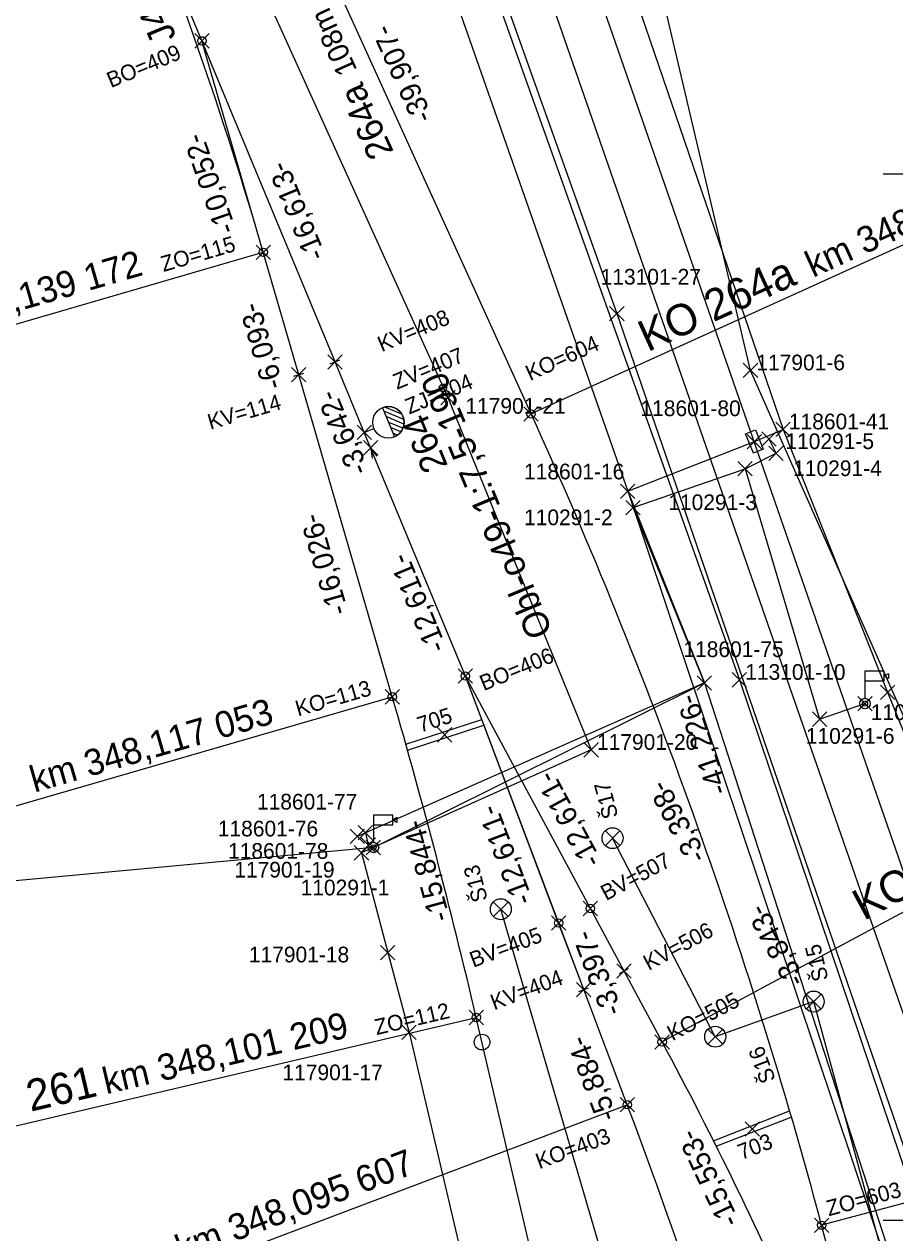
# Model space of a CAD drawing. Extents: x -821029 to -820632, y -1070881 to -1069931.
# Drawn here: x -820842.3 to -820800.7, y -1070400.6 to -1070342.9 of the extents above; entities that cross this region are included whole.
import ezdxf

# ---------------------------------------------------------------- set-up
doc = ezdxf.new("R2010")
doc.units = 0
for name, color, linetype in [('_PS_SO_číslo', 7, 'Continuous'), ('PS-11-02-31', 7, 'Continuous'), ('PS-11-02-41', 7, 'Continuous'), ('PS-11-02-91', 7, 'Continuous'), ('PS-11-02-92', 7, 'Continuous'), ('Sit', 7, 'Continuous'), ('SO-11-10-01', 7, 'Continuous'), ('SO-11-31-01', 7, 'Continuous'), ('SO-11-50-01', 7, 'Continuous'), ('SO-11-79-01', 7, 'Continuous'), ('SO-11-86-01', 7, 'Continuous'), ('Sttaniceni a namezniky', 7, 'Continuous'), ('VB_PS-11-02-91', 7, 'Continuous'), ('VB_SO-11-10-01', 7, 'Continuous'), ('VB_SO-11-31-01', 7, 'Continuous'), ('VB_SO-11-79-01', 7, 'Continuous'), ('VB_SO-11-86-01', 7, 'Continuous')]:
    doc.layers.add(name, color=color, linetype=linetype)

msp = doc.modelspace()

# ---------------------------------------------------------------- linework, layer by layer
at = {"layer": '_PS_SO_číslo'}
msp.add_line((-820825.628, -1070382.193), (-820859.303, -1070385.322), dxfattribs=at)
at = {"layer": 'PS-11-02-31'}
for points in [[(-820959.278, -1070122.218), (-820934.84, -1070144.095), (-820933.002, -1070146.602), (-820925.146, -1070161.738), (-820918.63, -1070175.611), (-820911.367, -1070188.874), (-820902.582, -1070186.65), (-820896.686, -1070196.978), (-820870.459, -1070236.453), (-820846.568, -1070277.079), (-820842.598, -1070282.108), (-820813.472, -1070365.169), (-820809.802, -1070374.33), (-820792.803, -1070426.722), (-820792.342, -1070428.474), (-820790.079, -1070430.856), (-820788.925, -1070435.581), (-820780.392, -1070470.858), (-820770.551, -1070511.609), (-820767.886, -1070524.681), (-820765.297, -1070562.399), (-820759.609, -1070562.181)], [(-820834.739, -1070280.72), (-820830.77, -1070287.401), (-820826.598, -1070295.778), (-820822.74, -1070307.417), (-820822.402, -1070310.542), (-820820.817, -1070316.363), (-820815.079, -1070335.816), (-820806.043, -1070362.212), (-820801.047, -1070374.777), (-820795.979, -1070387.28), (-820794.84, -1070387.997), (-820792.153, -1070393.193), (-820783.482, -1070412.233), (-820783.598, -1070416.458), (-820783.598, -1070418.019), (-820782.431, -1070424.351)], [(-820813.213, -1070365.954), (-820807.856, -1070364.093), (-820806.374, -1070363.352), (-820806.71, -1070362.68)], [(-820825.628, -1070382.193), (-820809.802, -1070374.33)]]:
    msp.add_lwpolyline(points, dxfattribs=at)
msp.add_lwpolyline([(-820807.368, -1070362.238), (-820806.994, -1070363.166), (-820807.458, -1070363.353), (-820807.832, -1070362.425)], close=True, dxfattribs=at)
at = {"layer": 'PS-11-02-41'}
for points in [[(-820882.988, -1070201.129), (-820875.537, -1070207.75), (-820872.787, -1070212.312), (-820866.572, -1070222.102), (-820863.695, -1070232.226), (-820854.155, -1070247.197), (-820844.785, -1070263.708), (-820834.739, -1070280.72), (-820830.77, -1070287.401), (-820826.598, -1070295.778), (-820822.74, -1070307.417), (-820822.402, -1070310.542), (-820820.817, -1070316.363), (-820815.079, -1070335.816), (-820806.043, -1070362.212), (-820801.047, -1070374.777), (-820795.979, -1070387.28), (-820794.84, -1070387.997), (-820792.153, -1070393.193), (-820783.482, -1070412.233), (-820783.598, -1070416.458), (-820783.598, -1070418.019), (-820782.431, -1070424.351)], [(-820813.472, -1070365.169), (-820807.413, -1070362.796), (-820806.043, -1070362.212)]]:
    msp.add_lwpolyline(points, dxfattribs=at)
at = {"layer": 'PS-11-02-91'}
for p, q in [((-820802.127, -1070374.234), (-820802.127, -1070375.064)), ((-820801.004, -1070373.887), (-820801.204, -1070374.003)), ((-820801.004, -1070374.118), (-820801.204, -1070374.003)), ((-820801.004, -1070373.887), (-820801.004, -1070374.118)), ((-820802.127, -1070375.314), (-820802.127, -1070375.314)), ((-820825.628, -1070381.113), (-820825.628, -1070381.943)), ((-820824.505, -1070380.767), (-820824.704, -1070380.882)), ((-820824.505, -1070380.998), (-820824.704, -1070380.882)), ((-820824.505, -1070380.767), (-820824.505, -1070380.998)), ((-820825.628, -1070382.193), (-820825.628, -1070382.193))]:
    msp.add_line(p, q, dxfattribs=at)
for points in [[(-820825.628, -1070382.193), (-820809.802, -1070374.33), (-820813.213, -1070365.954), (-820807.856, -1070364.093), (-820806.374, -1070363.352), (-820806.71, -1070362.68)], [(-820807.856, -1070364.093), (-820804.293, -1070376.062), (-820802.127, -1070375.314)]]:
    msp.add_lwpolyline(points, dxfattribs=at)
for points in [[(-820801.204, -1070373.772), (-820802.127, -1070373.772), (-820802.127, -1070374.234), (-820801.204, -1070374.234)], [(-820824.704, -1070380.651), (-820825.628, -1070380.651), (-820825.628, -1070381.113), (-820824.704, -1070381.113)]]:
    msp.add_lwpolyline(points, close=True, dxfattribs=at)
for centre, radius in [((-820802.127, -1070375.314), 0.25), ((-820802.127, -1070375.314), 0.125), ((-820825.628, -1070382.193), 0.25), ((-820825.628, -1070382.193), 0.125)]:
    msp.add_circle(centre, radius, dxfattribs=at)
at = {"layer": 'PS-11-02-92'}
for points in [[(-820882.988, -1070201.129), (-820875.537, -1070207.75), (-820872.787, -1070212.312), (-820866.572, -1070222.102), (-820863.695, -1070232.226), (-820854.155, -1070247.197), (-820844.785, -1070263.708), (-820834.739, -1070280.72), (-820830.77, -1070287.401), (-820826.598, -1070295.778), (-820822.74, -1070307.417), (-820822.402, -1070310.542), (-820820.817, -1070316.363), (-820815.079, -1070335.816), (-820806.043, -1070362.212), (-820801.047, -1070374.777), (-820795.979, -1070387.28), (-820794.84, -1070387.997), (-820792.153, -1070393.193), (-820783.482, -1070412.233), (-820783.598, -1070416.458), (-820783.598, -1070418.019), (-820782.431, -1070424.351)], [(-820813.472, -1070365.169), (-820807.413, -1070362.796), (-820806.043, -1070362.212)]]:
    msp.add_lwpolyline(points, dxfattribs=at)
at = {"layer": 'Sit'}
for p, q in [((-820801.25, -1070350), (-820800, -1070350)), ((-820801.25, -1070400), (-820800, -1070400))]:
    msp.add_line(p, q, dxfattribs=at)
at = {"layer": 'SO-11-10-01'}
for p, q in [((-820818.089, -1070361.478), (-820834.599, -1070325.146)), ((-820795.329, -1070351.135), (-820818.089, -1070361.478)), ((-820854.904, -1070360.722), (-820830.896, -1070353.751)), ((-820827.694, -1070359.088), (-820827.232, -1070358.896)), ((-820826.067, -1070362.356), (-820827.463, -1070358.992)), ((-820829.437, -1070359.672), (-820828.957, -1070359.532)), ((-820824.726, -1070374.992), (-820829.197, -1070359.602)), ((-820825.2, -1070361.184), (-820824.625, -1070362.57)), ((-820824.177, -1070361.738), (-820825.134, -1070361.343)), ((-820824.277, -1070361.481), (-820825.081, -1070361.148)), ((-820824.169, -1070361.958), (-820825.026, -1070361.604)), ((-820826.067, -1070362.356), (-820825.605, -1070362.164)), ((-820824.218, -1070362.154), (-820824.917, -1070361.865)), ((-820824.317, -1070362.33), (-820824.809, -1070362.126)), ((-820824.472, -1070362.482), (-820824.701, -1070362.387)), ((-820848.74, -1070381.942), (-820824.726, -1070374.992)), ((-820824.082, -1070377.256), (-820820.453, -1070376.071)), ((-820824.002, -1070377.546), (-820820.347, -1070376.352)), ((-820822.226, -1070376.808), (-820822.226, -1070376.808)), ((-820785.407, -1070377.264), (-820811.823, -1070391.484)), ((-820813.865, -1070388.219), (-820813.425, -1070387.981)), ((-820811.823, -1070391.484), (-820813.645, -1070388.1)), ((-820815.809, -1070389.067), (-820815.341, -1070388.891)), ((-820813.495, -1070394.483), (-820815.575, -1070388.979)), ((-820845.048, -1070396.034), (-820820.711, -1070390.317)), ((-820780.049, -1070393.776), (-820804.198, -1070400.243)), ((-820841.558, -1070405.088), (-820813.495, -1070394.483)), ((-820809.372, -1070396.202), (-820805.73, -1070394.783)), ((-820809.238, -1070396.472), (-820805.647, -1070395.072)), ((-820807.511, -1070395.638), (-820807.511, -1070395.638)), ((-820802.989, -1070404.758), (-820804.198, -1070400.243))]:
    msp.add_line(p, q, dxfattribs=at)
for points in [[(-820827.463, -1070358.992), (-820833.83, -1070343.648), (-820837.557, -1070334.666)], [(-820827.463, -1070358.992), (-820833.83, -1070343.648), (-820837.557, -1070334.666)], [(-820829.197, -1070359.602), (-820830.896, -1070353.751), (-820833.83, -1070343.648)], [(-820829.197, -1070359.602), (-820830.896, -1070353.751), (-820833.83, -1070343.648)], [(-820815.575, -1070388.979), (-820821.234, -1070374.004), (-820826.067, -1070362.356)], [(-820815.575, -1070388.979), (-820816.776, -1070385.801), (-820821.234, -1070374.004), (-820826.067, -1070362.356)], [(-820825.456, -1070363.491), (-820825.76, -1070363.095), (-820825.695, -1070363.591)], [(-820813.645, -1070388.1), (-820815.256, -1070385.108), (-820821.234, -1070374.004)], [(-820813.645, -1070388.1), (-820815.256, -1070385.108), (-820821.234, -1070374.004)], [(-820791.836, -1070436.403), (-820804.578, -1070389.555), (-820809.286, -1070391.234), (-820814.195, -1070381.747)], [(-820804.905, -1070439.605), (-820811.403, -1070412.909), (-820819.538, -1070385.143)], [(-820761.019, -1070645.411), (-820786.886, -1070534.867), (-820787.456, -1070532.433), (-820788.025, -1070529.999), (-820808.595, -1070442.095), (-820809.131, -1070439.803), (-820809.668, -1070437.51), (-820820.711, -1070390.317)]]:
    msp.add_lwpolyline(points, dxfattribs=at)
for centre, radius in [((-820833.83, -1070343.648), 0.2), ((-820830.896, -1070353.751), 0.2), ((-820824.912, -1070361.877), 0.75), ((-820818.089, -1070361.478), 0.2), ((-820821.234, -1070374.004), 0.2), ((-820824.726, -1070374.992), 0.2), ((-820814.195, -1070381.747), 0.5), ((-820819.538, -1070385.143), 0.5), ((-820815.256, -1070385.108), 0.2), ((-820816.776, -1070385.801), 0.2), ((-820804.578, -1070389.555), 0.5), ((-820820.711, -1070390.317), 0.2), ((-820809.286, -1070391.234), 0.5), ((-820811.823, -1070391.484), 0.2), ((-820813.495, -1070394.483), 0.2), ((-820804.198, -1070400.243), 0.2)]:
    msp.add_circle(centre, radius, dxfattribs=at)
msp.add_arc((-820824.912, -1070361.877), 0.75, 292.53459, 112.53459, dxfattribs=at)
for centre, major_axis, ratio, start_param, end_param in [((-821013.359, -1070406.731), (42.747, 185.129), 0.999991, 5.221901, 5.328341), ((-821045.682, -1070464.899), (-139.528, 207.442), 0.999954, 4.381904, 4.546806), ((-821102.722, -1070456.202), (-73.521, 290.852), 0.96534, 4.694931, 4.747744), ((-820979.107, -1070481.534), (-110.746, 154.387), 0.9999, 4.502101, 4.583959), ((-821056.703, -1070486.397), (38.305, 257.163), 0.999985, 5.090175, 5.221577)]:
    msp.add_ellipse(centre, major_axis=major_axis, ratio=ratio, start_param=start_param, end_param=end_param, dxfattribs=at)
at = {"layer": 'SO-11-31-01'}
for points in [[(-820926.07, -1070123.29), (-820916.95, -1070167.12), (-820908.61, -1070171.6), (-820902.99, -1070184.31), (-820895.92, -1070196.33), (-820868.5, -1070237.37), (-820845.66, -1070276.46), (-820841.66, -1070281.51), (-820839.82, -1070285.2), (-820808.13, -1070374.18), (-820790.33, -1070426.97), (-820782.93, -1070433.41), (-820769.19, -1070488.5), (-820779.762, -1070491.365)], [(-820832.57, -1070337.97), (-820821.56, -1070335.44), (-820813.99, -1070356.68), (-820798.47, -1070401.74), (-820795.5, -1070403.96), (-820793.85, -1070408.69), (-820790.57, -1070418.13), (-820788.93, -1070422.85), (-820783.27, -1070428.36), (-820780.97, -1070427.76), (-820780.24, -1070428.17), (-820779.88, -1070429.72), (-820781.01, -1070429.99)]]:
    msp.add_lwpolyline(points, dxfattribs=at)
at = {"layer": 'SO-11-50-01'}
for points in [[(-820831.742, -1070299.721), (-820794.486, -1070406.873), (-820788.19, -1070424.98)], [(-820815.774, -1070338.796), (-820798.172, -1070389.423), (-820789.142, -1070415.392), (-820782.756, -1070425.414), (-820778.113, -1070440.812), (-820778.3, -1070451.359), (-820766.965, -1070499.852)]]:
    msp.add_lwpolyline(points, dxfattribs=at)
at = {"layer": 'SO-11-79-01'}
for points in [[(-820832.859, -1070278.435), (-820856.812, -1070291.29), (-820851.463, -1070300.374), (-820846.113, -1070309.459), (-820839.296, -1070322.503), (-820836.663, -1070328.485), (-820822.067, -1070360.696), (-820815.218, -1070377.527), (-820826.198, -1070382.449), (-820824.947, -1070387.213), (-820823.927, -1070391.029), (-820782.064, -1070569.191)], [(-820761.036, -1070511.475), (-820774.105, -1070459.005), (-820777.683, -1070442.395), (-820780.824, -1070405.778), (-820791.175, -1070389.775), (-820795.413, -1070386.908), (-820807.598, -1070359.392), (-820815.489, -1070325.838), (-820825.29, -1070295.054), (-820830.464, -1070283.216), (-820832.859, -1070278.435)]]:
    msp.add_lwpolyline(points, dxfattribs=at)
at = {"layer": 'SO-11-86-01'}
msp.add_line((-820826.013, -1070381.49), (-820825.873, -1070382.083), dxfattribs=at)
for points in [[(-820870.459, -1070236.454), (-820846.568, -1070277.079), (-820842.598, -1070282.108), (-820813.472, -1070365.169), (-820792.803, -1070426.722), (-820792.342, -1070428.474), (-820790.079, -1070430.857), (-820788.924, -1070435.581), (-820780.392, -1070470.858), (-820770.551, -1070511.609), (-820767.886, -1070524.681), (-820765.297, -1070562.4), (-820759.609, -1070562.181), (-820765.131, -1070563.533), (-820782.387, -1070567.755), (-820781.928, -1070569.717), (-820782.387, -1070567.755)], [(-820844.785, -1070263.708), (-820834.739, -1070280.72), (-820830.77, -1070287.401), (-820826.598, -1070295.778), (-820822.74, -1070307.417), (-820822.402, -1070310.542), (-820820.817, -1070316.363), (-820815.079, -1070335.816), (-820806.043, -1070362.212), (-820801.047, -1070374.777), (-820795.979, -1070387.28), (-820794.84, -1070387.997), (-820792.153, -1070393.193), (-820783.482, -1070412.233), (-820783.598, -1070416.458), (-820783.598, -1070418.019), (-820782.431, -1070424.351), (-820780.96, -1070434.384), (-820773.909, -1070463.726), (-820769.347, -1070482.633)], [(-820813.472, -1070365.169), (-820807.413, -1070362.796), (-820806.043, -1070362.212)], [(-820809.802, -1070374.33), (-820826.013, -1070381.49), (-820826.393, -1070381.664)]]:
    msp.add_lwpolyline(points, dxfattribs=at)
msp.add_lwpolyline([(-820807.368, -1070362.238), (-820806.994, -1070363.166), (-820807.458, -1070363.353), (-820807.832, -1070362.425)], close=True, dxfattribs=at)
at = {"layer": 'Sttaniceni a namezniky'}
msp.add_circle((-820820.436, -1070391.494), 0.375, dxfattribs=at)
at = {"layer": 'VB_PS-11-02-91'}
for p, q in [((-820807.054, -1070363.023), (-820806.367, -1070362.336)), ((-820806.367, -1070363.023), (-820807.054, -1070362.336)), ((-820806.718, -1070363.696), (-820806.03, -1070363.009)), ((-820806.03, -1070363.696), (-820806.718, -1070363.009)), ((-820808.199, -1070364.437), (-820807.512, -1070363.75)), ((-820807.512, -1070364.437), (-820808.199, -1070363.75)), ((-820813.557, -1070366.298), (-820812.869, -1070365.611)), ((-820812.869, -1070366.298), (-820813.557, -1070365.611)), ((-820802.471, -1070375.657), (-820801.784, -1070374.97)), ((-820801.784, -1070375.657), (-820802.471, -1070374.97)), ((-820804.637, -1070376.405), (-820803.95, -1070375.718)), ((-820803.95, -1070376.405), (-820804.637, -1070375.718)), ((-820825.972, -1070382.537), (-820825.284, -1070381.849)), ((-820825.284, -1070382.537), (-820825.972, -1070381.849))]:
    msp.add_line(p, q, dxfattribs=at)
at = {"layer": 'VB_SO-11-10-01'}
for p, q in [((-820834.174, -1070343.992), (-820833.487, -1070343.304)), ((-820833.487, -1070343.992), (-820834.174, -1070343.304)), ((-820831.24, -1070354.095), (-820830.552, -1070353.408)), ((-820830.552, -1070354.095), (-820831.24, -1070353.408)), ((-820827.807, -1070359.336), (-820827.119, -1070358.648)), ((-820827.119, -1070359.336), (-820827.807, -1070358.648)), ((-820829.541, -1070359.945), (-820828.853, -1070359.258)), ((-820828.853, -1070359.945), (-820829.541, -1070359.258)), ((-820818.433, -1070361.822), (-820817.745, -1070361.134)), ((-820817.745, -1070361.822), (-820818.433, -1070361.134)), ((-820826.411, -1070362.7), (-820825.723, -1070362.012)), ((-820825.723, -1070362.7), (-820826.411, -1070362.012)), ((-820826.411, -1070362.7), (-820825.723, -1070362.012)), ((-820825.723, -1070362.7), (-820826.411, -1070362.012)), ((-820826.104, -1070363.439), (-820825.417, -1070362.751)), ((-820825.417, -1070363.439), (-820826.104, -1070362.751)), ((-820821.578, -1070374.348), (-820820.89, -1070373.66)), ((-820820.89, -1070374.348), (-820821.578, -1070373.66)), ((-820825.07, -1070375.336), (-820824.383, -1070374.648)), ((-820824.383, -1070375.336), (-820825.07, -1070374.648)), ((-820822.57, -1070377.152), (-820821.882, -1070376.464)), ((-820821.882, -1070377.152), (-820822.57, -1070376.464)), ((-820814.539, -1070382.091), (-820813.851, -1070381.403)), ((-820813.851, -1070382.091), (-820814.539, -1070381.403)), ((-820819.882, -1070385.487), (-820819.194, -1070384.799)), ((-820819.194, -1070385.487), (-820819.882, -1070384.799)), ((-820815.6, -1070385.452), (-820814.912, -1070384.764)), ((-820814.912, -1070385.452), (-820815.6, -1070384.764)), ((-820817.12, -1070386.144), (-820816.432, -1070385.457)), ((-820816.432, -1070386.144), (-820817.12, -1070385.457)), ((-820813.989, -1070388.444), (-820813.301, -1070387.756)), ((-820813.301, -1070388.444), (-820813.989, -1070387.756)), ((-820815.918, -1070389.323), (-820815.231, -1070388.636)), ((-820815.231, -1070389.323), (-820815.918, -1070388.636)), ((-820804.922, -1070389.899), (-820804.234, -1070389.211)), ((-820804.234, -1070389.899), (-820804.922, -1070389.211)), ((-820821.055, -1070390.661), (-820820.367, -1070389.973)), ((-820820.367, -1070390.661), (-820821.055, -1070389.973)), ((-820809.63, -1070391.578), (-820808.942, -1070390.89)), ((-820808.942, -1070391.578), (-820809.63, -1070390.89)), ((-820812.167, -1070391.828), (-820811.48, -1070391.14)), ((-820811.48, -1070391.828), (-820812.167, -1070391.14)), ((-820813.839, -1070394.827), (-820813.151, -1070394.139)), ((-820813.151, -1070394.827), (-820813.839, -1070394.139)), ((-820807.855, -1070395.982), (-820807.167, -1070395.294)), ((-820807.167, -1070395.982), (-820807.855, -1070395.294)), ((-820804.542, -1070400.587), (-820803.854, -1070399.9)), ((-820803.854, -1070400.587), (-820804.542, -1070399.9))]:
    msp.add_line(p, q, dxfattribs=at)
at = {"layer": 'VB_SO-11-31-01'}
for p, q in [((-820814.334, -1070357.024), (-820813.646, -1070356.336)), ((-820813.646, -1070357.024), (-820814.334, -1070356.336)), ((-820808.474, -1070374.524), (-820807.786, -1070373.836)), ((-820807.786, -1070374.524), (-820808.474, -1070373.836))]:
    msp.add_line(p, q, dxfattribs=at)
at = {"layer": 'VB_SO-11-79-01'}
for p, q in [((-820807.942, -1070359.736), (-820807.254, -1070359.048)), ((-820807.254, -1070359.736), (-820807.942, -1070359.048)), ((-820822.411, -1070361.04), (-820821.723, -1070360.352)), ((-820821.723, -1070361.04), (-820822.411, -1070360.352)), ((-820815.562, -1070377.871), (-820814.874, -1070377.183)), ((-820814.874, -1070377.871), (-820815.562, -1070377.183)), ((-820826.542, -1070382.793), (-820825.854, -1070382.105)), ((-820825.854, -1070382.793), (-820826.542, -1070382.105)), ((-820825.291, -1070387.557), (-820824.603, -1070386.869)), ((-820824.603, -1070387.557), (-820825.291, -1070386.869)), ((-820824.271, -1070391.373), (-820823.583, -1070390.685)), ((-820823.583, -1070391.373), (-820824.271, -1070390.685))]:
    msp.add_line(p, q, dxfattribs=at)
at = {"layer": 'VB_SO-11-86-01'}
for p, q in [((-820806.387, -1070362.556), (-820805.699, -1070361.868)), ((-820805.699, -1070362.556), (-820806.387, -1070361.868)), ((-820807.757, -1070363.14), (-820807.069, -1070362.452)), ((-820807.069, -1070363.14), (-820807.757, -1070362.452)), ((-820813.816, -1070365.513), (-820813.128, -1070364.825)), ((-820813.128, -1070365.513), (-820813.816, -1070364.825)), ((-820810.146, -1070374.674), (-820809.458, -1070373.986)), ((-820809.458, -1070374.674), (-820810.146, -1070373.986)), ((-820801.391, -1070375.121), (-820800.703, -1070374.433)), ((-820800.703, -1070375.121), (-820801.391, -1070374.433)), ((-820826.357, -1070381.834), (-820825.669, -1070381.146)), ((-820825.669, -1070381.834), (-820826.357, -1070381.146)), ((-820826.737, -1070382.008), (-820826.049, -1070381.32)), ((-820826.049, -1070382.008), (-820826.737, -1070381.32)), ((-820826.217, -1070382.427), (-820825.529, -1070381.739)), ((-820825.529, -1070382.427), (-820826.217, -1070381.739))]:
    msp.add_line(p, q, dxfattribs=at)

# ---------------------------------------------------------------- texts
at = {"layer": 'SO-11-10-01'}
for s, height, rotation, p in [('J49-1:9-190', 1.25, 112.53737, (-820835.039, -1070343.462)), ('108m', 1, 114.43801, (-820826.392, -1070345.033)), ('-39,907-', 1, 114.43801, (-820822.763, -1070347.305)), ('264a', 1.25, 114.43801, (-820824.642, -1070348.95)), ('-10,052-', 1, 109.12983, (-820832.17, -1070352.683)), ('-16,613-', 1, 112.53603, (-820827.889, -1070353.913)), ('km 348,129 023', 1.25, 24.43846, (-820804.613, -1070354.977)), ('km 348,139 172', 1.25, 16.19212, (-820848.096, -1070358.166)), ('KO 264a ', 1.5, 24.43846, (-820812.519, -1070358.529)), ('-6,093-', 1, 106.19212, (-820829.925, -1070360.144)), ('Obl-o49-1:7,5-190', 1.25, 112.53459, (-820817.043, -1070371.898)), ('-3,642-', 1, 112.53758, (-820825.834, -1070364.162)), ('264', 1.25, 112.53459, (-820822.052, -1070363.96)), ('-16,026-', 1, 106.19928, (-820826.814, -1070370.936)), ('-12,611-', 1, 112.53459, (-820822.108, -1070372.643)), ('-41,226-', 1, 108.57781, (-820808.636, -1070379.499)), ('km 348,117 053', 1.25, 16.14159, (-820841.838, -1070379.574)), ('-12,611-', 1, 118.29645, (-820814.693, -1070382.831)), ('-3,398-', 1, 118.29961, (-820809.654, -1070382.624)), ('-12,611-', 1, 110.70121, (-820817.983, -1070384.725)), ('-15,844-', 1, 105.47845, (-820821.949, -1070385.595)), ('KO 264 ', 1.5, 28.2952, (-820802.182, -1070385.711)), ('-3,843-', 1, 118.29874, (-820804.947, -1070388.536)), ('-3,397-', 1, 110.7014, (-820813.71, -1070390.016)), ('km 348,101 209', 1.25, 13.22041, (-820838.411, -1070393.988)), ('-5,884-', 1, 110.70193, (-820813.969, -1070395.064)), ('ZO 261 ', 1.5, 13.22041, (-820845.277, -1070395.586)), ('-15,553-', 1, 115.36887, (-820808.101, -1070400.062)), ('km 348,095 607', 1.25, 20.702, (-820834.8, -1070401.983))]:
    msp.add_text(s, height=height, rotation=rotation, dxfattribs=at).set_placement(p)
at = {"layer": 'VB_PS-11-02-91'}
for s, p in [(' 110291-5', (-820806.208, -1070363.155)), (' 110291-4', (-820805.838, -1070364.446)), (' 110291-3', (-820811.808, -1070366.071)), (' 110291-2', (-820818.706, -1070366.792)), (' 110291-7', (-820802.127, -1070376.103)), (' 110291-6', (-820805.231, -1070377.235)), (' 110291-1', (-820829.389, -1070384.481))]:
    msp.add_text(s, height=0.75, dxfattribs=at).set_placement(p)
at = {"layer": 'VB_SO-11-10-01'}
for s, rotation, p in [('BO=409', 22.53737, (-820838.183, -1070345.907)), ('ZO=115', 16.19212, (-820835.669, -1070354.695)), ('KV=408', 22.53758, (-820825.236, -1070358.528)), ('KO=604', 24.43801, (-820818.14, -1070359.91)), ('ZV=407', 22.53459, (-820824.502, -1070360.322)), ('ZJ=804', 22.53459, (-820823.916, -1070361.507)), ('KV=114', 16.19928, (-820833.431, -1070362.236)), ('BO=406', 22.53459, (-820820.354, -1070374.724)), ('KO=113', 16.19928, (-820829.234, -1070375.936)), ('705', 18.07858, (-820823.385, -1070376.714)), ('Š17', 104.57523, (-820813.917, -1070380.71)), ('BV=507', 28.29961, (-820814.502, -1070384.755)), ('Š13', 104.57523, (-820820.159, -1070384.69)), ('KV=506', 28.29874, (-820812.469, -1070388.089)), ('BV=405', 20.7014, (-820820.854, -1070387.942)), ('Š15', 103.17006, (-820803.87, -1070388.492)), ('KV=404', 20.70193, (-820819.857, -1070389.974)), ('KO=505', 27.71372, (-820811.333, -1070391.459)), ('ZO=112', 13.17006, (-820825.479, -1070391.159)), ('Š16', 110.70193, (-820806.384, -1070393.285)), ('KO=403', 20.45524, (-820817.699, -1070397.57)), ('703', 21.29632, (-820808.028, -1070397.134)), ('ZO=603', 14.99064, (-820803.857, -1070399.816))]:
    msp.add_text(s, height=0.75, rotation=rotation, dxfattribs=at).set_placement(p)
at = {"layer": 'VB_SO-11-31-01'}
for s, p in [(' 113101-27', (-820815.045, -1070355.294)), (' 113101-10', (-820808.13, -1070374.18))]:
    msp.add_text(s, height=0.75, dxfattribs=at).set_placement(p)
at = {"layer": 'VB_SO-11-79-01'}
for s, p in [(' 117901-6', (-820807.598, -1070359.392)), (' 117901-21', (-820821.51, -1070361.467)), (' 117901-20', (-820815.218, -1070377.527)), (' 117901-19', (-820832.562, -1070383.628)), (' 117901-18', (-820831.863, -1070387.682)), (' 117901-17', (-820830.257, -1070393.315))]:
    msp.add_text(s, height=0.75, dxfattribs=at).set_placement(p)
at = {"layer": 'VB_SO-11-86-01'}
for s, p in [(' 118601-80', (-820813.14, -1070361.58)), (' 118601-41', (-820806.043, -1070362.212)), (' 118601-16', (-820818.707, -1070364.601)), (' 118601-75', (-820811.087, -1070373.093)), (' 118601-77', (-820831.477, -1070380.379)), (' 118601-76', (-820833.348, -1070381.664)), (' 118601-78', (-820832.859, -1070382.734))]:
    msp.add_text(s, height=0.75, dxfattribs=at).set_placement(p)

doc.saveas('drawing.dxf')
